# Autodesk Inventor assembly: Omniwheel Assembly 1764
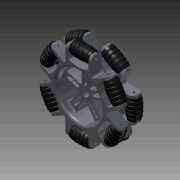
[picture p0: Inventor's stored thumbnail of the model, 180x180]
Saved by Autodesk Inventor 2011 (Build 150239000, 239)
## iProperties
Created: 2007-11
Part Number: Omniwheel Assembly 1764
Document SubType Name: Assembly
Designer: lwoods
Mass: 807.037 g
Surface Area: 1296.28 cm^2
Volume: 334.333 cm^3
Density: 2.41387 g/cm^3
Author: lwoods
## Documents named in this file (4)
- R:\CAD Archives\Wheels\Omniwheel 1764\Omniwheel Assembly 1764.iam
- R:\CAD Archives\Wheels\Omniwheel 1764\Roller Axle V4 1764.ipt
- R:\CAD Archives\Wheels\Omniwheel 1764\Omnidrive 1764.ipt
- R:\CAD Archives\Wheels\Omniwheel 1764\Roller Assembly 1764.iam
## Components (25 placed, 3 different names)
1. Omnidrive 1764:1 — Insert:1, Insert:2, Insert:3, Insert:4, Insert:5, Insert:6, Insert:7, Insert:8, Insert:9, Insert:10, Insert:11, Insert:12, Insert:16, Insert:17, Insert:19, Insert:20
2. Roller Axle V4 1764:1 — Insert:11, Insert:24
3. Roller Axle V4 1764:2 — Insert:8
4. Roller Axle V4 1764:3 — Insert:12, Insert:23
5. Roller Axle V4 1764:4 — Insert:10, Insert:22
6. Roller Axle V4 1764:5 — Insert:3, Insert:14
7. Roller Axle V4 1764:6 — Insert:4, Insert:18
8. Roller Axle V4 1764:7 — Insert:6
9. Roller Axle V4 1764:8 — Insert:2
10. Roller Axle V4 1764:9 — Insert:1, Insert:13
11. Roller Axle V4 1764:10 — Insert:5
12. Roller Axle V4 1764:11 — Insert:9, Insert:15
13. Roller Axle V4 1764:12 — Insert:7, Insert:21
14. Roller Assembly 1764:1 [sub-assembly] — Insert:18
15. Roller Assembly 1764:2 [sub-assembly] — Insert:20
16. Roller Assembly 1764:3 [sub-assembly] — Insert:17
17. Roller Assembly 1764:4 [sub-assembly] — Insert:19
18. Roller Assembly 1764:5 [sub-assembly] — Insert:21
19. Roller Assembly 1764:6 [sub-assembly] — Insert:22
20. Roller Assembly 1764:7 [sub-assembly] — Insert:23
21. Roller Assembly 1764:8 [sub-assembly] — Insert:24
22. Roller Assembly 1764:9 [sub-assembly] — Insert:16
23. Roller Assembly 1764:10 [sub-assembly] — Insert:15
24. Roller Assembly 1764:11 [sub-assembly] — Insert:13
25. Roller Assembly 1764:12 [sub-assembly] — Insert:14
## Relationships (24: Insert 24)
- Insert:1: Omnidrive 1764:1 ↔ Roller Axle V4 1764:9
- Insert:2: Omnidrive 1764:1 ↔ Roller Axle V4 1764:8
- Insert:3: Omnidrive 1764:1 ↔ Roller Axle V4 1764:5
- Insert:4: Omnidrive 1764:1 ↔ Roller Axle V4 1764:6
- Insert:5: Omnidrive 1764:1 ↔ Roller Axle V4 1764:10
- Insert:6: Omnidrive 1764:1 ↔ Roller Axle V4 1764:7
- Insert:7: Omnidrive 1764:1 ↔ Roller Axle V4 1764:12
- Insert:8: Omnidrive 1764:1 ↔ Roller Axle V4 1764:2
- Insert:9: Omnidrive 1764:1 ↔ Roller Axle V4 1764:11
- Insert:10: Omnidrive 1764:1 ↔ Roller Axle V4 1764:4
- Insert:11: Omnidrive 1764:1 ↔ Roller Axle V4 1764:1
- Insert:12: Omnidrive 1764:1 ↔ Roller Axle V4 1764:3
- Insert:13: Roller Axle V4 1764:9 ↔ Roller Assembly 1764:11
- Insert:14: Roller Axle V4 1764:5 ↔ Roller Assembly 1764:12
- Insert:15: Roller Axle V4 1764:11 ↔ Roller Assembly 1764:10
- Insert:16: Omnidrive 1764:1 ↔ Roller Assembly 1764:9
- Insert:17: Omnidrive 1764:1 ↔ Roller Assembly 1764:3
- Insert:18: Roller Axle V4 1764:6 ↔ Roller Assembly 1764:1
- Insert:19: Omnidrive 1764:1 ↔ Roller Assembly 1764:4
- Insert:20: Omnidrive 1764:1 ↔ Roller Assembly 1764:2
- Insert:21: Roller Axle V4 1764:12 ↔ Roller Assembly 1764:5
- Insert:22: Roller Axle V4 1764:4 ↔ Roller Assembly 1764:6
- Insert:23: Roller Axle V4 1764:3 ↔ Roller Assembly 1764:7
- Insert:24: Roller Axle V4 1764:1 ↔ Roller Assembly 1764:8
